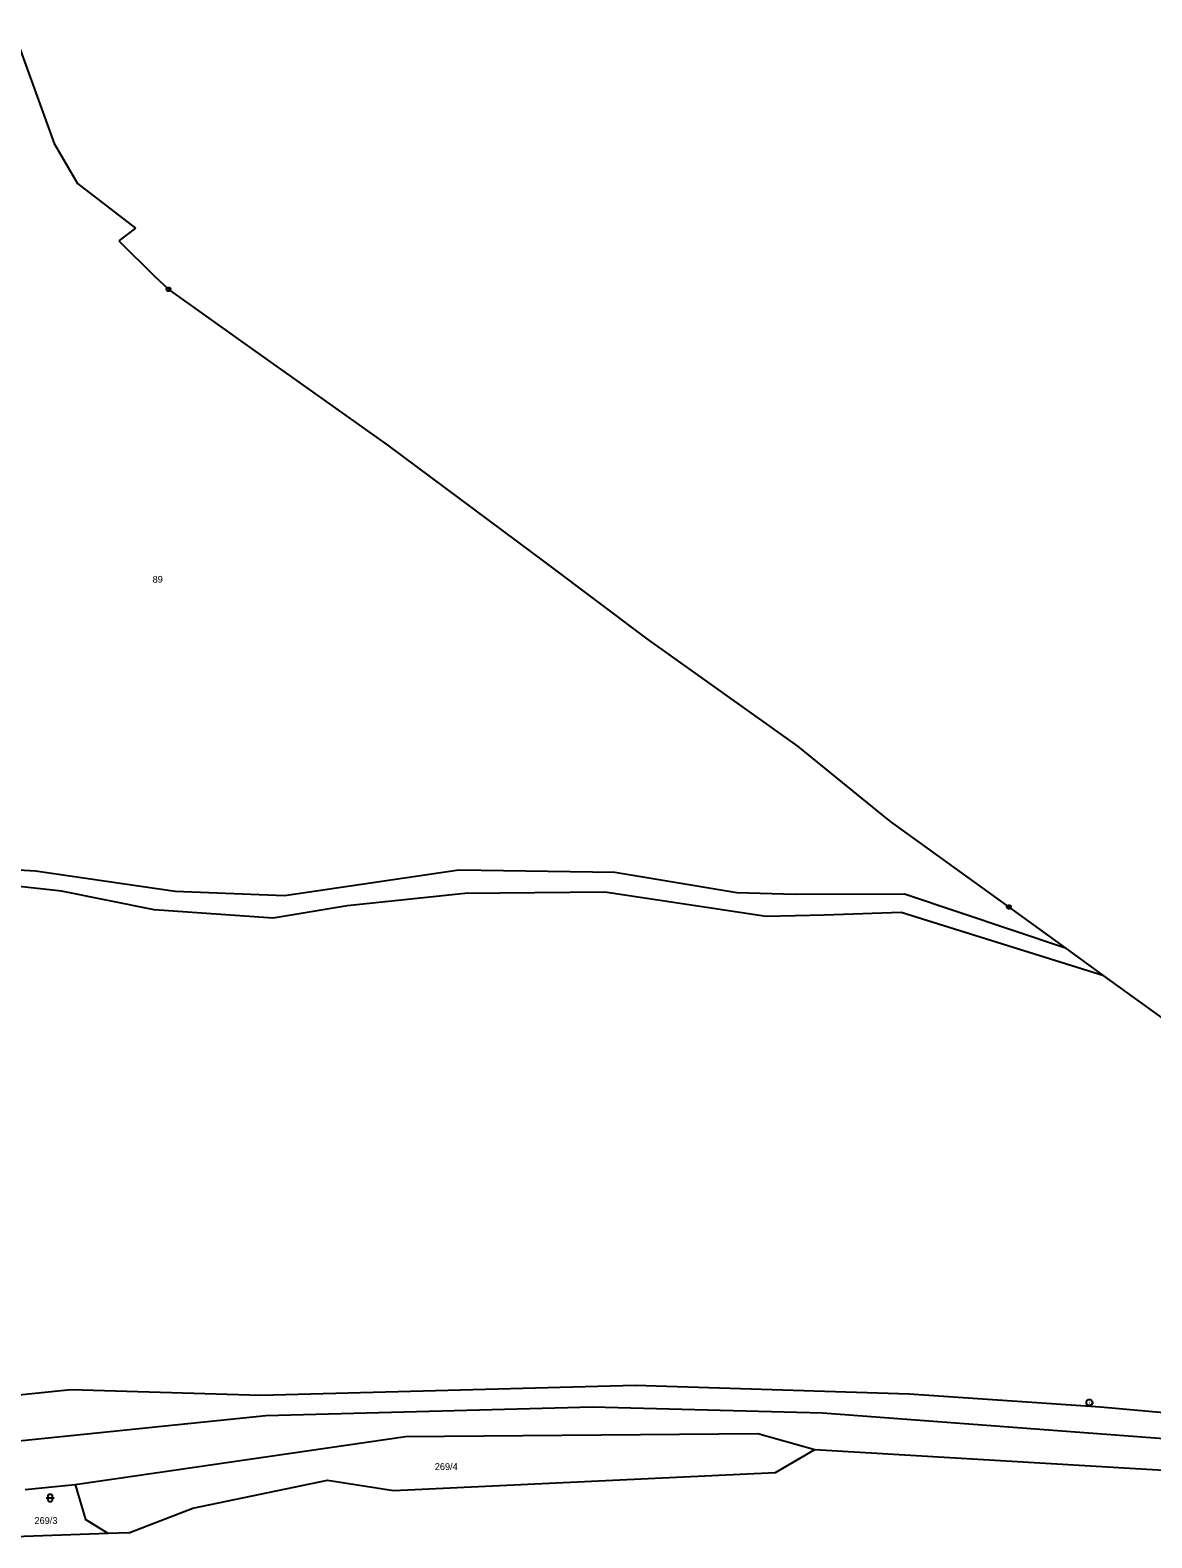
# Model space of a CAD drawing. Extents: x -780000 to -777378, y -1011169 to -1009297.
# Drawn here: x -778181.9 to -777903.4, y -1010270.3 to -1009896 of the extents above; entities that cross this region are included whole.
import ezdxf

# ---------------------------------------------------------------- set-up
doc = ezdxf.new("R2010")
doc.units = 0
for name, color, linetype in [('Default', 7, 'Continuous'), ('KN_HRANICE', 7, 'Continuous'), ('KN_KULTURY', 7, 'Continuous'), ('KN_PARCELY', 7, 'Continuous'), ('KN_VEDENI', 7, 'Continuous')]:
    doc.layers.add(name, color=color, linetype=linetype)

# ---------------------------------------------------------------- blocks, each defined once
blk = doc.blocks.new('101')
at = {"layer": 'Default'}
blk.add_line((-0.05, 0), (0.05, 0), dxfattribs=at)
blk.add_lwpolyline([(0.19, 0.72), (0.53, 0.53), (0.72, 0.19), (0.72, -0.2), (0.53, -0.54), (0.19, -0.73), (-0.2, -0.73), (-0.54, -0.54), (-0.73, -0.2), (-0.73, 0.19), (-0.54, 0.53), (-0.2, 0.72), (0.19, 0.72)], dxfattribs=at)
blk = doc.blocks.new('316')
at = {"layer": 'Default'}
for points in [[(-1, 1), (0.27, 1), (1, 1)], [(-0.5, 1.5), (-0.4, 1.79), (-0.15, 1.97), (0.16, 1.97), (0.41, 1.79), (0.51, 1.5), (0.51, 0.5), (0.41, 0.21), (0.16, 0.03), (-0.15, 0.03), (-0.4, 0.21), (-0.5, 0.5), (-0.5, 1.5)]]:
    blk.add_lwpolyline(points, dxfattribs=at)
blk = doc.blocks.new('105')
at = {"layer": 'Default'}
blk.add_line((-0.12, 0), (0.12, 0), dxfattribs=at)
blk.add_lwpolyline([(0.15, 0.48), (0.4, 0.3), (0.5, 0.01), (0.4, -0.28), (0.15, -0.46), (-0.16, -0.46), (-0.41, -0.28), (-0.51, 0.01), (-0.41, 0.3), (-0.16, 0.48), (0.15, 0.48)], dxfattribs=at)

msp = doc.modelspace()

# ---------------------------------------------------------------- linework, layer by layer
at = {"layer": 'KN_HRANICE'}
for p, q in [((-778186.19, -1009895.98), (-778176.01, -1009924.09)), ((-778176.01, -1009924.09), (-778170.19, -1009934.08)), ((-778170.19, -1009934.08), (-778155.75, -1009945.17)), ((-778155.75, -1009945.17), (-778159.95, -1009948.33)), ((-778159.95, -1009948.33), (-778150.97, -1009957.16)), ((-778150.97, -1009957.16), (-778147.56, -1009960.33)), ((-778129.11, -1009973.45), (-778147.56, -1009960.33)), ((-778093.24, -1009998.98), (-778129.11, -1009973.45)), ((-778053.72, -1010028.31), (-778093.24, -1009998.98)), ((-778028.76, -1010047.15), (-778053.72, -1010028.31)), ((-777991.28, -1010073.76), (-778028.76, -1010047.15)), ((-777969.15, -1010091.83), (-777991.28, -1010073.76)), ((-777967.71, -1010092.87), (-777969.15, -1010091.83)), ((-777938.89, -1010113.7), (-777967.71, -1010092.87)), ((-778239.95, -1010101.4), (-778180.65, -1010104.69)), ((-778180.65, -1010104.69), (-778145.9, -1010109.73)), ((-778118.76, -1010110.86), (-778075.46, -1010104.51)), ((-778075.46, -1010104.51), (-778036.74, -1010105.05)), ((-778036.74, -1010105.05), (-778006.46, -1010110.09)), ((-778174.14, -1010109.8), (-778185.39, -1010108.53)), ((-778151.12, -1010114.44), (-778174.14, -1010109.8)), ((-778145.9, -1010109.73), (-778118.76, -1010110.86)), ((-778074.01, -1010110.38), (-778103.23, -1010113.41)), ((-778039.22, -1010109.98), (-778074.01, -1010110.38)), ((-777999.17, -1010116.04), (-778039.22, -1010109.98)), ((-778006.46, -1010110.09), (-777991.99, -1010110.55)), ((-777991.99, -1010110.55), (-777964.85, -1010110.4)), ((-777964.85, -1010110.4), (-777924.86, -1010123.86)), ((-778121.64, -1010116.47), (-778151.12, -1010114.44)), ((-778103.23, -1010113.41), (-778121.64, -1010116.47)), ((-777984.81, -1010115.73), (-777999.17, -1010116.04)), ((-777965.67, -1010115.09), (-777984.81, -1010115.73)), ((-777915.32, -1010130.76), (-777965.67, -1010115.09)), ((-777924.86, -1010123.86), (-777938.89, -1010113.7)), ((-777915.32, -1010130.76), (-777924.86, -1010123.86)), ((-777861.25, -1010169.9), (-777915.32, -1010130.76)), ((-778124.65, -1010234.94), (-778031.73, -1010232.44)), ((-778031.73, -1010232.44), (-777963.69, -1010234.58)), ((-778205.12, -1010236.96), (-778171.83, -1010233.51)), ((-778171.83, -1010233.51), (-778124.65, -1010234.94)), ((-777963.69, -1010234.58), (-777916.19, -1010237.79)), ((-777916.19, -1010237.79), (-777862.6, -1010242.68)), ((-778170.74, -1010257.06), (-778088.74, -1010245.14)), ((-778088.74, -1010245.14), (-778001.23, -1010244.44)), ((-778001.23, -1010244.44), (-777987.12, -1010248.38)), ((-777996.83, -1010254.14), (-777987.12, -1010248.38)), ((-777987.12, -1010248.38), (-777867.3, -1010255.54)), ((-778091.73, -1010258.61), (-777996.83, -1010254.14)), ((-778183.15, -1010258.35), (-778170.74, -1010257.06)), ((-778170.74, -1010257.06), (-778168.18, -1010265.77)), ((-778141.57, -1010263.01), (-778108.14, -1010255.99)), ((-778108.14, -1010255.99), (-778091.73, -1010258.61)), ((-778162.58, -1010269.25), (-778168.18, -1010265.77)), ((-778157.45, -1010269.07), (-778141.57, -1010263.01)), ((-778162.58, -1010269.25), (-778193.74, -1010270.34)), ((-778157.45, -1010269.07), (-778162.58, -1010269.25))]:
    msp.add_line(p, q, dxfattribs=at)
at = {"layer": 'KN_VEDENI'}
for p, q in [((-778203.65, -1010248.13), (-778123.44, -1010240)), ((-778123.44, -1010240), (-778042.28, -1010237.85)), ((-778042.28, -1010237.85), (-777985.16, -1010239.29)), ((-777985.16, -1010239.29), (-777867.19, -1010248.13))]:
    msp.add_line(p, q, dxfattribs=at)

# ---------------------------------------------------------------- block references
at = {"layer": 'KN_KULTURY'}
msp.add_blockref('316', (-778176.96, -1010261.44), dxfattribs=at)
at = {"layer": 'KN_PARCELY'}
for name, p in [('105', (-778147.56, -1009960.33)), ('105', (-778147.56, -1009960.33)), ('105', (-778147.56, -1009960.33)), ('105', (-777938.89, -1010113.7)), ('101', (-777918.91, -1010236.74))]:
    msp.add_blockref(name, p, dxfattribs=at)

# ---------------------------------------------------------------- texts
for s, p in [('89', (-778151.54, -1010033.19)), ('269/4', (-778081.47, -1010253.49)), ('269/3', (-778180.86, -1010266.89))]:
    msp.add_text(s, height=1.7, dxfattribs=at).set_placement(p)

doc.saveas('drawing.dxf')
